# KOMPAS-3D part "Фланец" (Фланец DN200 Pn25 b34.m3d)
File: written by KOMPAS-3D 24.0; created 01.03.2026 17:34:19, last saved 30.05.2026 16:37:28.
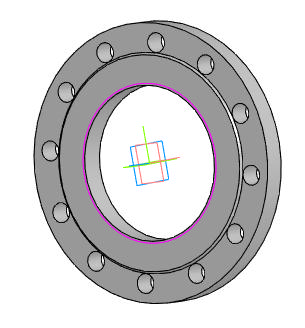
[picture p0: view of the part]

Document properties: Автор: R2D2; Полное имя файла: E:\Работа\Зайцев\GVWR2121M-2W-F-ОСТ Задвижка клиновая 30с964нж DN.ru Ду50-300 Ру25\исходные материалы\DN200\Фланец DN200 Pn25 b34.m3d

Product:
- Part/product: Фланец
    Масса: 16.307666
    additional columns: Типовые

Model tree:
1. Эскиз:2
2. Элемент вращения:1
     Угол 1 = 360
3. Эскиз:3  (with: Грань.Элемент вращения:1)
4. Элемент выдавливания:2
     Расстояние 1 = 3; Расстояние 2 = 31
5. Массив по концентрической сетке:1  (with: Элемент выдавливания:2, Эскиз:3, Грань.Элемент вращения:1)  (12 pattern instances)
     Шаг 2 = 360
6. Эскиз:4  (with: Грань.Элемент вращения:1)
7. Элемент выдавливания:3
     Расстояние 2 = 4

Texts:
  Линейный размер с обрывом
